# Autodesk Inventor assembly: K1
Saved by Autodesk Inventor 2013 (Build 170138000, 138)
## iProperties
Created: 2021-02
Part Number: K1
Document SubType Name: Assembly
Designer: Fede
Author: Fede
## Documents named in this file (2)
- C:\0000 FEDE\16GB\0000 INTERIOR\DE_TMP_BAS\BAS_DTON - demora conexion al energizar\DTON_MANUAL\img\INVENTOR\BAS_DTON - SIN R\K1.iam
- C:\0000 FEDE\16GB\0000 INTERIOR\DE_TMP_BAS\BAS_DTON - demora conexion al energizar\DTON_MANUAL\img\INVENTOR\BAS_DTON - SIN R\relay.iam
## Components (1 placed, 1 different names)
1. relay:1 [sub-assembly]
